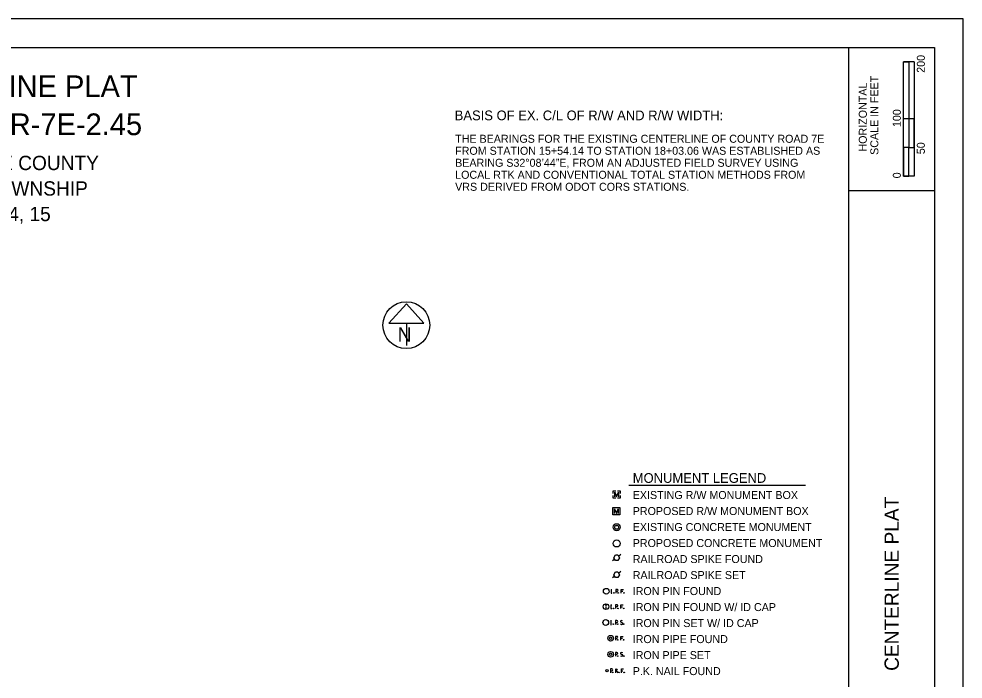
# Model space of a CAD drawing. Extents: x 0 to 34, y 0 to 22.
# Drawn here: x 17.48 to 34, y 10.45 to 22 of the extents above; entities that cross this region are included whole.
import ezdxf

# ---------------------------------------------------------------- set-up
doc = ezdxf.new("R2010")
doc.units = 0
for name, color, linetype in [('_CIVIL_CONSTRUCTION', 7, 'Continuous'), ('GE_X_Alignment_100_Bearings', 7, 'Continuous'), ('RW_X_CL_100_Curve_Data', 7, 'Continuous'), ('SH_Masking', 7, 'Continuous'), ('SH_Text', 7, 'Continuous')]:
    doc.layers.add(name, color=color, linetype=linetype)

msp = doc.modelspace()

# ---------------------------------------------------------------- linework, layer by layer
at = {"layer": '_CIVIL_CONSTRUCTION'}
for p, q in [((32, 0.5), (32, 21.5)), ((32, 19), (33.5, 19))]:
    msp.add_line(p, q, dxfattribs=at)
msp.add_lwpolyline([(1.5, 21.5), (33.5, 21.5), (33.5, 0.5), (1.5, 0.5)], close=True, dxfattribs=at)
at = {"layer": 'GE_X_Alignment_100_Bearings'}
for p, q in [((24.258, 17.017), (23.95, 16.675)), ((24.565, 16.675), (24.258, 17.017)), ((23.95, 16.675), (24.565, 16.675)), ((24.258, 16.675), (24.258, 16.289)), ((28.15, 13.846), (31.242, 13.846)), ((27.938, 13.68), (27.938, 13.68)), ((27.933, 13.389), (27.933, 13.389)), ((28.011, 12.628), (27.971, 12.598)), ((27.904, 12.548), (27.864, 12.518)), ((27.904, 12.251), (27.864, 12.221)), ((28.011, 12.331), (27.971, 12.301)), ((27.839, 12.02), (27.856, 12.02)), ((27.839, 12.02), (27.856, 12.02)), ((27.839, 11.953), (27.856, 11.953)), ((27.847, 11.953), (27.847, 12.02)), ((27.924, 11.988), (27.951, 11.988)), ((28.018, 11.953), (28.018, 12.02)), ((28.018, 12.02), (28.056, 12.02)), ((28.018, 11.988), (28.045, 11.988)), ((27.835, 11.751), (27.851, 11.751)), ((27.835, 11.751), (27.851, 11.751)), ((27.843, 11.684), (27.843, 11.751)), ((28.013, 11.684), (28.013, 11.751)), ((28.013, 11.751), (28.052, 11.751)), ((27.751, 11.722), (27.751, 11.686)), ((27.835, 11.684), (27.851, 11.684)), ((27.92, 11.719), (27.946, 11.719)), ((28.013, 11.718), (28.041, 11.718)), ((27.83, 11.474), (27.847, 11.474)), ((27.83, 11.474), (27.847, 11.474)), ((27.83, 11.408), (27.847, 11.408)), ((27.839, 11.408), (27.839, 11.474)), ((27.915, 11.442), (27.942, 11.442)), ((28.01, 11.451), (28.04, 11.435)), ((27.917, 11.167), (27.943, 11.167)), ((28.01, 11.132), (28.01, 11.199)), ((28.01, 11.199), (28.049, 11.199)), ((28.01, 11.166), (28.038, 11.166)), ((27.917, 10.885), (27.943, 10.885)), ((28.011, 10.893), (28.042, 10.878)), ((27.829, 10.598), (27.855, 10.598)), ((27.922, 10.563), (27.922, 10.63)), ((27.922, 10.588), (27.954, 10.63)), ((27.932, 10.601), (27.96, 10.563)), ((28.02, 10.563), (28.02, 10.63)), ((28.02, 10.63), (28.059, 10.63)), ((28.02, 10.598), (28.048, 10.598))]:
    msp.add_line(p, q, dxfattribs=at)
for points in [[(27.875, 13.695), (27.875, 13.742), (27.922, 13.742)], [(27.907, 13.638), (27.907, 13.721), (27.938, 13.638), (27.968, 13.721), (27.968, 13.638)], [(27.952, 13.742), (28, 13.742), (28, 13.695)], [(27.922, 13.617), (27.875, 13.617), (27.875, 13.664)], [(28, 13.664), (28, 13.617), (27.952, 13.617)], [(27.87, 13.452), (27.995, 13.452), (27.995, 13.327), (27.87, 13.327), (27.87, 13.452)], [(27.902, 13.347), (27.902, 13.431), (27.933, 13.347), (27.964, 13.431), (27.964, 13.347)], [(27.951, 12.02), (27.924, 12.02), (27.924, 11.953)], [(27.946, 11.751), (27.92, 11.751), (27.92, 11.684)], [(27.942, 11.474), (27.915, 11.474), (27.915, 11.408)], [(27.943, 11.199), (27.917, 11.199), (27.917, 11.132)], [(27.943, 10.917), (27.917, 10.917), (27.917, 10.851)], [(27.855, 10.63), (27.829, 10.63), (27.829, 10.563)]]:
    msp.add_lwpolyline(points, dxfattribs=at)
for points in [[(27.919, 12.623), (27.956, 12.623), (27.986, 12.573), (27.956, 12.523), (27.919, 12.523), (27.889, 12.573)], [(27.919, 12.326), (27.956, 12.326), (27.986, 12.276), (27.956, 12.226), (27.919, 12.226), (27.889, 12.276)]]:
    msp.add_lwpolyline(points, close=True, dxfattribs=at)
for centre, radius in [((24.258, 16.643), 0.41), ((27.938, 13.107), 0.0625), ((27.938, 13.107), 0.0333), ((27.938, 12.825), 0.0625), ((27.756, 11.987), 0.05), ((27.888, 11.958), 0.00583), ((27.964, 11.958), 0.00583), ((28.066, 11.958), 0.00583), ((27.751, 11.718), 0.05), ((27.751, 11.745), 0.00667), ((27.883, 11.689), 0.00583), ((27.96, 11.689), 0.00583), ((28.062, 11.689), 0.00583), ((27.747, 11.441), 0.05), ((27.879, 11.412), 0.00583), ((27.956, 11.412), 0.00583), ((28.062, 11.412), 0.00583), ((27.833, 11.165), 0.05), ((27.833, 11.165), 0.0206), ((27.957, 11.137), 0.00583), ((28.059, 11.137), 0.00583), ((27.833, 10.884), 0.05), ((27.833, 10.884), 0.0208), ((27.957, 10.855), 0.00583), ((28.064, 10.855), 0.00583), ((27.769, 10.597), 0.0207), ((27.869, 10.568), 0.00583), ((27.978, 10.568), 0.00583), ((28.069, 10.568), 0.00583)]:
    msp.add_circle(centre, radius, dxfattribs=at)
for centre, radius, start, end in [((27.948, 12.004), 0.0162, 278.8803, 81.1197), ((27.944, 11.735), 0.0162, 278.8803, 81.1197), ((27.94, 11.458), 0.0162, 278.8803, 81.1197), ((28.016, 11.46), 0.0118, 126.2587, 236.3675), ((28.025, 11.436), 0.0276, 223.6695, 304.3963), ((28.026, 11.439), 0.0349, 61.3463, 118.6537), ((28.03, 11.424), 0.0148, 311.4883, 47.9358), ((27.941, 11.183), 0.0162, 278.8803, 81.1197), ((27.941, 10.901), 0.0162, 278.8803, 81.1197), ((28.018, 10.903), 0.0118, 126.2587, 236.3675), ((28.027, 10.882), 0.0349, 61.3463, 118.6537), ((28.026, 10.878), 0.0276, 223.6695, 304.3963), ((28.032, 10.867), 0.0148, 311.4883, 47.9358), ((27.853, 10.614), 0.0162, 278.8803, 81.1197)]:
    msp.add_arc(centre, radius, start, end, dxfattribs=at)
at = {"layer": 'RW_X_CL_100_Curve_Data'}
msp.add_circle((24.258, 16.643), 0.41, dxfattribs=at)
at = {"layer": 'SH_Masking'}
msp.add_lwpolyline([(0, 0), (34, 0), (34, 22), (0, 22)], close=True, dxfattribs=at)
at = {"layer": 'SH_Text'}
for p, q in [((32.957, 19.25), (32.957, 21.25)), ((33.144, 21.25), (32.957, 21.25)), ((32.957, 20.25), (32.957, 21.25)), ((32.957, 21.25), (33.05, 21.25)), ((33.05, 21.25), (33.051, 21.25)), ((33.051, 21.25), (33.051, 20.25)), ((33.144, 21.25), (33.144, 19.25)), ((33.051, 20.25), (32.957, 20.25)), ((33.143, 20.25), (33.05, 20.25)), ((33.05, 20.25), (33.05, 19.75)), ((33.143, 19.75), (33.143, 20.25)), ((33.05, 19.75), (32.957, 19.75)), ((32.957, 19.75), (32.957, 19.25)), ((33.05, 19.75), (33.143, 19.75)), ((33.05, 19.25), (33.05, 19.75)), ((33.144, 19.25), (32.957, 19.25)), ((32.957, 19.25), (33.05, 19.25))]:
    msp.add_line(p, q, dxfattribs=at)

# ---------------------------------------------------------------- texts
at = {"layer": 'GE_X_Alignment_100_Bearings'}
for s, height, p in [('BASIS OF EX. C/L OF R/W AND R/W WIDTH:', 0.17, (25.104, 20.227)), ('THE BEARINGS FOR THE EXISTING CENTERLINE OF COUNTY ROAD 7E ', 0.14, (25.112, 19.833)), ('FROM STATION 15+54.14 TO STATION 18+03.06 WAS ESTABLISHED AS ', 0.14, (25.112, 19.623)), ('BEARING S32°08’44”E, FROM AN ADJUSTED FIELD SURVEY USING ', 0.14, (25.112, 19.413)), ('LOCAL RTK AND CONVENTIONAL TOTAL STATION METHODS FROM ', 0.14, (25.112, 19.203)), ('VRS DERIVED FROM ODOT CORS STATIONS.', 0.14, (25.112, 18.993)), ('N', 0.25, (24.106, 16.352)), ('MONUMENT LEGEND', 0.17, (28.219, 13.884)), ('EXISTING R/W MONUMENT BOX', 0.14, (28.219, 13.601)), ('PROPOSED R/W MONUMENT BOX', 0.14, (28.219, 13.321)), ('EXISTING CONCRETE MONUMENT', 0.14, (28.219, 13.041)), ('PROPOSED CONCRETE MONUMENT', 0.14, (28.219, 12.761)), ('RAILROAD SPIKE FOUND', 0.14, (28.219, 12.481)), ('RAILROAD SPIKE SET', 0.14, (28.219, 12.201)), ('IRON PIN FOUND', 0.14, (28.219, 11.921)), ('IRON PIN FOUND W/ ID CAP', 0.14, (28.219, 11.641)), ('IRON PIN SET W/ ID CAP', 0.14, (28.219, 11.361)), ('IRON PIPE FOUND', 0.14, (28.219, 11.081)), ('IRON PIPE SET', 0.14, (28.219, 10.801)), ('P.K. NAIL FOUND', 0.14, (28.219, 10.521))]:
    msp.add_text(s, height=height, dxfattribs=at).set_placement(p)
at = {"layer": 'SH_Text'}
for s, height, p in [('200', 0.14, (33.33, 21.057)), ('SCALE IN FEET', 0.14, (32.517, 19.621)), ('HORIZONTAL', 0.14, (32.315, 19.679)), ('100', 0.14, (32.91, 20.107)), ('50', 0.14, (33.33, 19.633)), ('0', 0.14, (32.91, 19.211)), ('CENTERLINE PLAT', 0.25, (32.875, 10.595))]:
    msp.add_text(s, height=height, rotation=90, dxfattribs=at).set_placement(p)
for s, height, p in [('CENTERLINE PLAT', 0.38, (14.926, 20.631)), ('LAW-141 / CR-7E-2.45', 0.38, (14.41, 19.966)), ('LAWRENCE COUNTY', 0.25, (15.479, 19.355)), ('UPPER TOWNSHIP', 0.25, (15.639, 18.909)), ('SEC. 14, 15', 0.25, (16.233, 18.462))]:
    msp.add_text(s, height=height, dxfattribs=at).set_placement(p)

doc.saveas('drawing.dxf')
